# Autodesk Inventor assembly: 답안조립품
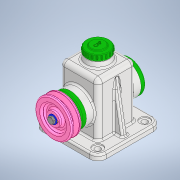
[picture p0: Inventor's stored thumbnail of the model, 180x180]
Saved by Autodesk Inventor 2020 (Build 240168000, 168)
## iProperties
Created: 2021-07
Part Number: 답안조립품
Document SubType Name: Assembly
Designer: Owner
Author: Owner
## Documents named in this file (14)
- C:\Users\Owner\Desktop\710715V1004\답안조립품.iam
- C:\Users\Owner\Desktop\710715V1004\본체.ipt
- C:\Users\Owner\Desktop\710715V1004\V-벨트풀리.ipt
- C:\Users\Owner\Desktop\710715V1004\뒤커버.ipt
- C:\Users\Owner\Desktop\710715V1004\멈춤링 15 x 1.ipt
- C:\Users\Owner\Desktop\710715V1004\베어링 15 x 35 x 11.ipt
- C:\Users\Owner\Desktop\710715V1004\볼트 M4 x 10.ipt
- C:\Users\Owner\Desktop\710715V1004\볼트 M6 x 12.ipt
- C:\Users\Owner\Desktop\710715V1004\상부캡.ipt
- C:\Users\Owner\Desktop\710715V1004\앞커버.ipt
- C:\Users\Owner\Desktop\710715V1004\오일실 15 25 7.ipt
- C:\Users\Owner\Desktop\710715V1004\와셔.ipt
- C:\Users\Owner\Desktop\710715V1004\축.ipt
- C:\Users\Owner\Desktop\710715V1004\키 5 x 5 x 14.ipt
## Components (1 placed, 1 different names)
1. V-벨트풀리:1
